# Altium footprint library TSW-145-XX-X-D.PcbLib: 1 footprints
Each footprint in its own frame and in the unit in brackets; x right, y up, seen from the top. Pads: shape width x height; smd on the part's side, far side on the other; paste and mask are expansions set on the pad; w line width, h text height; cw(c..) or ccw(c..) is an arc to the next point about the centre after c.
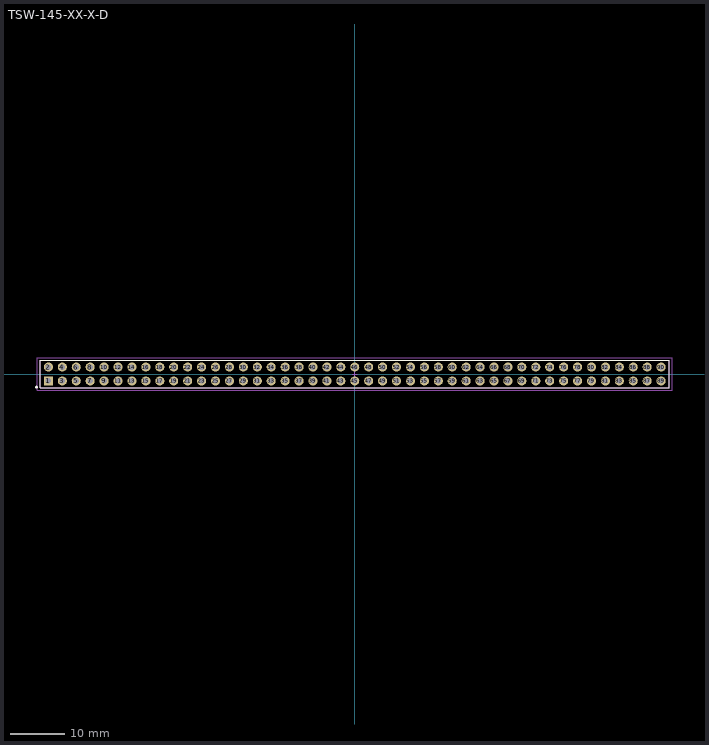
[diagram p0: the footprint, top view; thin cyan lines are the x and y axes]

## TSW-145-XX-X-D [mm] "2.54mm pitch, 90 pin, terminal strip; double row"
height 2.54
pads (90):
  rect 1.65x1.65 hole 1 mask+0: 1(-55.88,-1.27)
  round 1.65 hole 1 mask+0: 2(-55.88,1.27) 3(-53.34,-1.27) 4(-53.34,1.27) 5(-50.8,-1.27) 6(-50.8,1.27) 7(-48.26,-1.27) 8(-48.26,1.27) 9(-45.72,-1.27) 10(-45.72,1.27) 11(-43.18,-1.27) 12(-43.18,1.27) 13(-40.64,-1.27) 14(-40.64,1.27) 15(-38.1,-1.27) 16(-38.1,1.27) 17(-35.56,-1.27) 18(-35.56,1.27) 19(-33.02,-1.27) 20(-33.02,1.27) 21(-30.48,-1.27) 22(-30.48,1.27) 23(-27.94,-1.27) 24(-27.94,1.27) 25(-25.4,-1.27) 26(-25.4,1.27) 27(-22.86,-1.27) 28(-22.86,1.27) 29(-20.32,-1.27) 30(-20.32,1.27) 31(-17.78,-1.27) 32(-17.78,1.27) 33(-15.24,-1.27) 34(-15.24,1.27) 35(-12.7,-1.27) 36(-12.7,1.27) 37(-10.16,-1.27) 38(-10.16,1.27) 39(-7.62,-1.27) 40(-7.62,1.27) 41(-5.08,-1.27) 42(-5.08,1.27) 43(-2.54,-1.27) 44(-2.54,1.27) 45(0,-1.27) 46(0,1.27) 47(2.54,-1.27) 48(2.54,1.27) 49(5.08,-1.27) 50(5.08,1.27) 51(7.62,-1.27) 52(7.62,1.27) 53(10.16,-1.27) 54(10.16,1.27) 55(12.7,-1.27) 56(12.7,1.27) 57(15.24,-1.27) 58(15.24,1.27) 59(17.78,-1.27) 60(17.78,1.27) 61(20.32,-1.27) 62(20.32,1.27) 63(22.86,-1.27) 64(22.86,1.27) 65(25.4,-1.27) 66(25.4,1.27) 67(27.94,-1.27) 68(27.94,1.27) 69(30.48,-1.27) 70(30.48,1.27) 71(33.02,-1.27) 72(33.02,1.27) 73(35.56,-1.27) 74(35.56,1.27) 75(38.1,-1.27) 76(38.1,1.27) 77(40.64,-1.27) 78(40.64,1.27) 79(43.18,-1.27) 80(43.18,1.27) 81(45.72,-1.27) 82(45.72,1.27) 83(48.26,-1.27) 84(48.26,1.27) 85(50.8,-1.27) 86(50.8,1.27) 87(53.34,-1.27) 88(53.34,1.27) 89(55.88,-1.27) 90(55.88,1.27)
Top Overlay:
  circle w0.25: c-58.05,-2.4 r0.125
  lines w0.2: -57.4,-2.5 57.4,-2.5 57.4,2.5 -57.4,2.5 -57.4,-2.5
Mechanical 12:
  lines w0.001: -57.4,-2.5 57.4,-2.5 57.4,2.5 -57.4,2.5 -57.4,-2.5
Mechanical 13:
  lines w0.1: -57.4,-2.5 57.4,-2.5 57.4,2.5 -57.4,2.5 -57.4,-2.5
  text ".Designator" at 0,0 h1.52
Mechanical 15:
  lines w0.05: -0.5,0 0.5,0 ; 0,-0.5 0,0.5 ; -57.9,-3 57.9,-3 57.9,3 -57.9,3 -57.9,-3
